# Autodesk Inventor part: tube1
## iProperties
Shininess: 64.0
Length Units: 11269
Angle Units: 11279
Time Units: 11290
Mass Units: 11283
Length Display Precision: 3
Angle Display Precision: 2
Compacted: True
Part Number: tube1
Document SubType Name: Modeling
Created: 2003-07
Designer: JB
Density: 0.0
Volumn: 0.0
Area: 0.0
PropertySet Name: Model Information
Control State: 0
Master: False
Checked Out: False
Author: JB
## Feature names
1. Extrusion1
